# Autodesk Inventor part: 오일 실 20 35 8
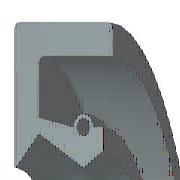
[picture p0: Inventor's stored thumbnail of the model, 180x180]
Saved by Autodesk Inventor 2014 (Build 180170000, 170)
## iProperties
IsCustomPart: 0
Created: 2018-09
Part Number: 오일 실 20 35 8
Material: 고무
Description: 오일-실
Document SubType Name: Modeling
Standard: KS B 2804
Standards Organization: KS
Language: ko-KR
Size Designation: D - 20 35 8
Categories: <MemberInstance><Categories><Category DisplayName="샤프트 부품" InternalName="7f7aeb1f-a693-4053-b835-cee3144e0d98" Mnemonic="SHFT"><Category DisplayName="실링" Intern
Density: 0.93 g/cm^3
Mass: 2.54606 g
Surface Area: 35.9421 cm^2
Volume: 2.7377 cm^3
Appearance: 보라색
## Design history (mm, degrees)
revolve "본체" stored, may be unused: angle "d17" = 90 deg
revolve "스프링1" stored, may be unused: angle "d18" = 90 deg
body "Solid1"
sketch "스케치1"
  geometry: L1 (0, 17.5)-(8, 17.5); L2 (8, 15.75)-(1.75, 15.75); L3 (1.75, 11.75)-(4.9, 10); L4 (4.9, 10)-(0, 10); L5 (0, 0)-(9.586, 0) reference; L6 (4.9, 10)-(6.3, 10.875); L7 (0, 18)-(0, -3) reference; L8 (-1.941, 0)-(11.507, 0) reference; L9 (4.2, 12.1)-(1.75, 12.71); L10 (1.75, 12.71)-(1.75, 15.75); L11 (0, 17.5)-(0, 10.088); L12 (4.9, 10)-(0, 10); L13 (1.75, 11.75)-(0.152, 10.028); L14 (8, 17.5)-(8, 15.75); L15 (5.6, 12.1)-(6.3, 12.1); L16 (6.3, 12.1)-(6.3, 10.875); C1 r 0.455 at (4.9, 12.1); A1 r 0.7 centre (4.9, 12.1) between (5.6, 12.1) and (4.2, 12.1); A2 r 0.088 centre (0.088, 10.088) between (0, 10.088) and (0.152, 10.028); 1 further point
  constraints: 28 end point, 5 horizontal alignment, 5 point on line, 4 point on circle, 4 vertical alignment, 3 centre point, 3 tangent, 2 collinear, 2 horizontal, 2 perpendicular, 1 coincident, 1 parallel
  dimensions: "d0" = 35 diameter of L1 L5 (= SD2); "d1" = 1.75 distance of L1.end L2.start (= SD); "d2" = 0.91 diameter of C1 (= SPDI); "d3" = 1.4 diameter of A1 (= SPDA); "d4" = 20 diameter of L3.end L5 (= NND); "d5" = 23.5 diameter of L3.start L5 (= TKDM); "d7" = 25.42 diameter of L9.end L5 (= TKDM + 0.24 x SWDT); "d8" = 1.75 distance between parallel lines of L11 L10 (= SD); "d9" = 4.9 distance from line of L11 C1.centre (= SPDST); "d10" = 24.2 diameter of C1.centre L5 (= HLDM); "d11" = 0.0875 radius of A2 (= 0.25 x LAB); "d12" = 6.3 distance between parallel lines of L11 L16 (= SDI); "d13" = 21.75 diameter of L6.end L5 (= ABDM); "d14" = 8 distance from line of L11 L1.end (= SWDT)
fillet "모깎기1" dims "d6" = 0.3 (= RR)
other parameters: "SD2" = 35 [user parameter; used in 1 equation term], "SWDT" = 8 [user parameter; used in 2 equation terms], "RR" = 0.3 [user parameter; used in 1 equation term], "SD" = 1.75 [user parameter; used in 2 equation terms], "NND" = 20 [user parameter; used in 1 equation term], "SPDA" = 1.4 [user parameter; used in 1 equation term], "SPDI" = 0.91 [user parameter; used in 1 equation term], "TKDM" = 23.5 [user parameter; used in 2 equation terms], "HLDM" = 24.2 [user parameter; used in 1 equation term], "ABDM" = 21.75 [user parameter; used in 1 equation term], "SDI" = 6.3 [user parameter; used in 1 equation term], "SPDST" = 4.9 [user parameter; used in 1 equation term], "LAB" = 0.35 [user parameter; used in 1 equation term], "d15" = 0, "d16" = 0, "d19" = 0
